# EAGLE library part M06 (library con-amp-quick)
AMP QUICK CONNECTOR
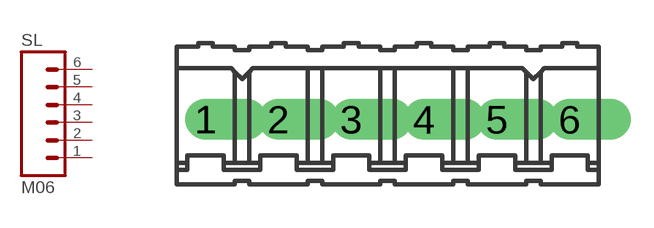
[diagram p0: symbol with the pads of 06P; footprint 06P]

Designator prefix SL

## M06  [06P]
1  1  pas
2  2  pas
3  3  pas
4  4  pas
5  5  pas
6  6  pas

## Footprint 06P (pad centres in mm)
AMP QUICK CONNECTOR
drill 0.914 offset: 1 -6.35,0; 2 -3.81,0; 3 -1.27,0; 4 1.27,0; 5 3.81,0; 6 6.35,0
